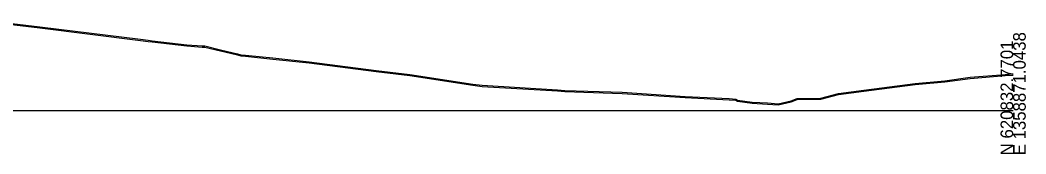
# Model space of a CAD drawing. Extents: x -26 to 803, y -27 to 3586.
# Drawn here: x 578.8 to 802.8, y 1990.3 to 2020.2 of the extents above; entities that cross this region are included whole.
import ezdxf

# ---------------------------------------------------------------- set-up
doc = ezdxf.new("R2010")
doc.units = 0
for name, color, linetype in [('DESIGN - SHEET - Light Grid', 7, 'Continuous'), ('SURVEY - GROUND - Bottom of Topsoil Layer', 7, 'Continuous'), ('SURVEY - GROUND - Top of Ground', 7, 'Continuous')]:
    doc.layers.add(name, color=color, linetype=linetype)

msp = doc.modelspace()

# ---------------------------------------------------------------- linework, layer by layer
at = {"layer": 'DESIGN - SHEET - Light Grid'}
msp.add_line((400, 2000), (800, 2000), dxfattribs=at)
at = {"layer": 'SURVEY - GROUND - Bottom of Topsoil Layer'}
for p, q in [((570.68, 2019.92), (583.24, 2018.44)), ((583.24, 2018.44), (605.6, 2015.64)), ((605.6, 2015.64), (607.33, 2015.42)), ((607.33, 2015.42), (608.21, 2015.31)), ((608.21, 2015.31), (615.98, 2014.39)), ((615.98, 2014.39), (619.4, 2014.15)), ((619.4, 2014.15), (619.99, 2014.14)), ((619.99, 2014.14), (623.43, 2013.28)), ((623.43, 2013.28), (627.2, 2012.42)), ((627.2, 2012.42), (628, 2012.2)), ((628, 2012.2), (629.05, 2012.1)), ((629.05, 2012.1), (635.14, 2011.48)), ((635.14, 2011.48), (643.18, 2010.62)), ((643.18, 2010.62), (658.09, 2008.68)), ((658.09, 2008.68), (665.63, 2007.78)), ((665.63, 2007.78), (679.62, 2005.64)), ((790.42, 2007.16), (798.24, 2007.81)), ((798.24, 2007.81), (800, 2007.89)), ((679.62, 2005.64), (681.71, 2005.38)), ((681.71, 2005.38), (698.54, 2004.35)), ((766.73, 2004.3), (778.21, 2005.77)), ((778.21, 2005.77), (784.78, 2006.38)), ((784.78, 2006.38), (790.42, 2007.16)), ((698.54, 2004.35), (700.12, 2004.22)), ((700.12, 2004.22), (712.95, 2003.8)), ((712.95, 2003.8), (726.93, 2002.86)), ((726.93, 2002.86), (736.78, 2002.39)), ((757.19, 2002.52), (761.11, 2003.57)), ((761.11, 2003.57), (766.73, 2004.3)), ((736.78, 2002.39), (738.2, 2002.29)), ((738.2, 2002.29), (738.63, 2002.07)), ((738.63, 2002.07), (741.84, 2001.64)), ((741.84, 2001.64), (745.29, 2001.42)), ((745.29, 2001.42), (747.69, 2001.24)), ((747.69, 2001.24), (750.55, 2001.91)), ((750.55, 2001.91), (751.92, 2002.42)), ((751.92, 2002.42), (757.19, 2002.52))]:
    msp.add_line(p, q, dxfattribs=at)
at = {"layer": 'SURVEY - GROUND - Top of Ground'}
msp.add_lwpolyline([(570.68, 2020.17), (583.24, 2018.69), (605.6, 2015.89), (607.33, 2015.67), (608.21, 2015.56), (615.98, 2014.64), (619.4, 2014.4), (619.99, 2014.39), (623.43, 2013.53), (627.2, 2012.67), (628, 2012.45), (629.05, 2012.35), (635.14, 2011.73), (643.18, 2010.87), (658.09, 2008.93), (665.63, 2008.03), (679.62, 2005.89), (681.71, 2005.63), (698.54, 2004.6), (700.12, 2004.47), (712.95, 2004.05), (726.93, 2003.11), (736.78, 2002.64), (738.2, 2002.54), (738.63, 2002.32), (741.84, 2001.89), (745.29, 2001.67), (747.69, 2001.49), (750.55, 2002.16), (751.92, 2002.67), (757.19, 2002.77), (761.11, 2003.82), (766.73, 2004.55), (778.21, 2006.02), (784.78, 2006.63), (790.42, 2007.41), (798.24, 2008.06), (800, 2008.14)], dxfattribs=at)

# ---------------------------------------------------------------- texts
at = {"layer": 'DESIGN - SHEET - Light Grid'}
for s, p in [('E 1358871.0438', (802.8, 1990)), ('N 620832.7701', (800, 1990))]:
    msp.add_text(s, height=2.8, rotation=90, dxfattribs=at).set_placement(p)

doc.saveas('drawing.dxf')
